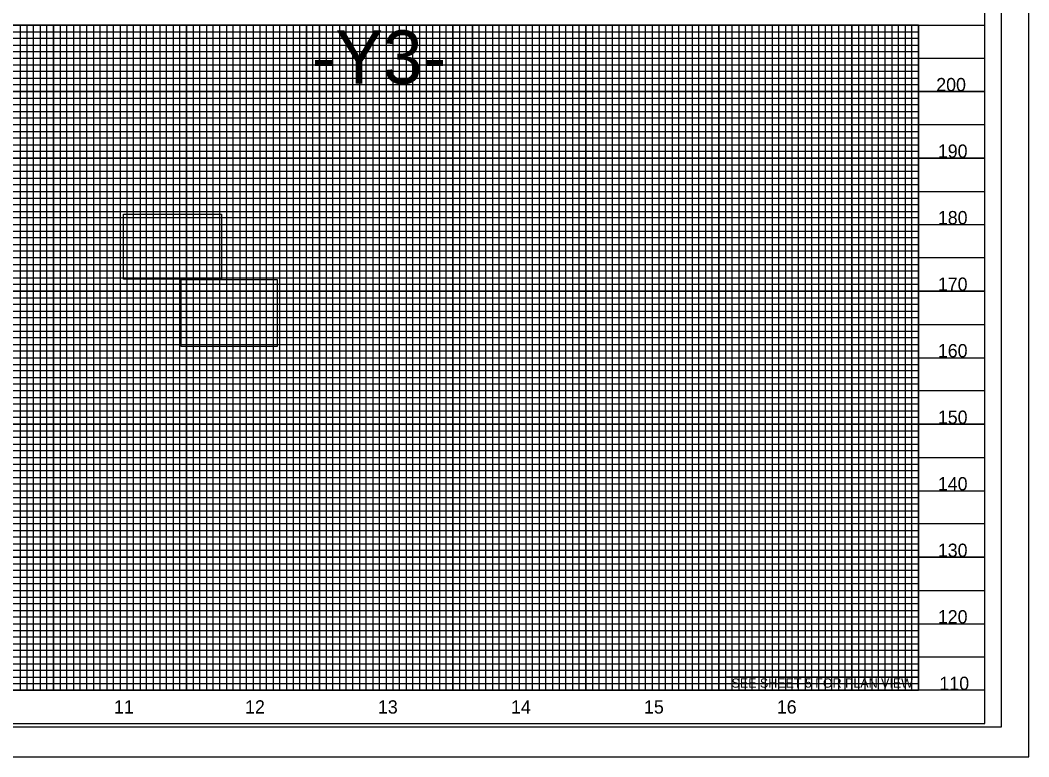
# Model space of a CAD drawing. Extents: x 1779926 to 1781626, y 618464 to 619564.
# Drawn here: x 1780868 to 1781626, y 618464 to 619018 of the extents above; entities that cross this region are included whole.
import ezdxf

# ---------------------------------------------------------------- set-up
doc = ezdxf.new("R2010")
doc.units = 0
for name, color, linetype in [('Exist Vertical Profile Horizontal Axis Label Major', 7, 'Continuous'), ('Exist Vertical Profile Vertical Axis Label', 7, 'Continuous'), ('Prop DSN Text', 7, 'Continuous'), ('Prop Grid Mask', 7, 'Continuous'), ('Sheet DOT Grid CELL', 7, 'Continuous'), ('Sheet Layout Profile Border Port 2', 7, 'Continuous'), ('Sheet Plot Border Inside CELL', 7, 'Continuous'), ('Sheet Plot Border Outside CELL', 7, 'Continuous'), ('Sheet Profile CELL', 7, 'Continuous'), ('Sheet Profile Grid Major CELL', 7, 'Continuous'), ('Sheet Profile Grid Middle CELL', 7, 'Continuous'), ('Sheet Profile Grid Minor CELL', 7, 'Continuous')]:
    doc.layers.add(name, color=color, linetype=linetype)

msp = doc.modelspace()

# ---------------------------------------------------------------- linework, layer by layer
at = {"layer": 'Prop Grid Mask'}
for points in [[(1781207.96, 619014.19), (1781083.09, 619014.19), (1781083.09, 618964.19), (1781207.96, 618964.19)], [(1780945.64, 618872.05), (1781019.12, 618872.05), (1781019.12, 618823.22), (1780945.64, 618823.22)], [(1780988.9, 618823.06), (1781061.03, 618823.06), (1781061.03, 618772.71), (1780988.9, 618772.71)], [(1781542.96, 618524.19), (1781397.96, 618524.19), (1781397.96, 618514.19), (1781542.96, 618514.19)]]:
    msp.add_lwpolyline(points, close=True, dxfattribs=at)
at = {"layer": 'Sheet DOT Grid CELL'}
for p, q in [((1780092.96, 619014.19), (1781592.85, 619014.19)), ((1780892.96, 619014.19), (1780892.96, 618514.19)), ((1780942.96, 619014.19), (1780942.96, 618514.19)), ((1780992.96, 619014.19), (1780992.96, 618514.19)), ((1781042.96, 619014.19), (1781042.96, 618514.19)), ((1781092.96, 619014.19), (1781092.96, 618514.19)), ((1781142.96, 619014.19), (1781142.96, 618514.19)), ((1781192.96, 619014.19), (1781192.96, 618514.19)), ((1781242.96, 619014.19), (1781242.96, 618514.19)), ((1781292.96, 619014.19), (1781292.96, 618514.19)), ((1781342.96, 619014.19), (1781342.96, 618514.19)), ((1781392.96, 619014.19), (1781392.96, 618514.19)), ((1781442.96, 619014.19), (1781442.96, 618514.19)), ((1781492.96, 619014.19), (1781492.96, 618514.19)), ((1781542.96, 619014.19), (1781542.96, 618514.19)), ((1780092.96, 618964.19), (1781592.85, 618964.19)), ((1780092.96, 618914.19), (1781592.85, 618914.19)), ((1780092.96, 618864.19), (1781592.85, 618864.19)), ((1780092.96, 618814.19), (1781592.85, 618814.19)), ((1780092.96, 618764.19), (1781592.85, 618764.19)), ((1780092.96, 618714.19), (1781592.85, 618714.19)), ((1780092.96, 618664.19), (1781592.85, 618664.19)), ((1780092.96, 618614.19), (1781592.85, 618614.19)), ((1780092.96, 618564.19), (1781592.85, 618564.19))]:
    msp.add_line(p, q, dxfattribs=at)
at = {"layer": 'Sheet Layout Profile Border Port 2'}
msp.add_line((1781542.96, 619014.19), (1781442.96, 619014.19), dxfattribs=at)
msp.add_lwpolyline([(1780142.96, 619014.19), (1781542.96, 619014.19), (1781542.96, 618514.19), (1780142.96, 618514.19)], close=True, dxfattribs=at)
msp.add_lwpolyline([(1781442.96, 619014.19), (1780142.96, 619014.19), (1780142.96, 618514.19), (1781542.96, 618514.19), (1781542.96, 619014.19)], dxfattribs=at)
at = {"layer": 'Sheet Plot Border Inside CELL'}
msp.add_lwpolyline([(1779938.96, 618486.64), (1781605.46, 618486.64), (1781605.46, 619541.74), (1779938.96, 619541.74)], close=True, dxfattribs=at)
at = {"layer": 'Sheet Plot Border Outside CELL'}
msp.add_lwpolyline([(1779925.96, 618464.19), (1781625.96, 618464.19), (1781625.96, 619564.19), (1779925.96, 619564.19)], close=True, dxfattribs=at)
at = {"layer": 'Sheet Profile CELL'}
for p, q in [((1780092.96, 619014.19), (1781592.96, 619014.19)), ((1781592.96, 618514.19), (1780092.96, 618514.19)), ((1780092.96, 618489.19), (1781592.96, 618489.19))]:
    msp.add_line(p, q, dxfattribs=at)
msp.add_lwpolyline([(1781592.96, 619539.19), (1780092.96, 619539.19), (1780092.96, 618489.19), (1781592.96, 618489.19)], close=True, dxfattribs=at)
at = {"layer": 'Sheet Profile Grid Major CELL'}
for p, q in [((1780892.96, 619014.19), (1780942.96, 619014.19)), ((1780992.96, 619014.19), (1781042.96, 619014.19)), ((1781092.96, 619014.19), (1781142.96, 619014.19)), ((1781192.96, 619014.19), (1781242.96, 619014.19)), ((1781292.96, 619014.19), (1781342.96, 619014.19)), ((1781392.96, 619014.19), (1781442.96, 619014.19)), ((1781492.96, 619014.19), (1781542.96, 619014.19)), ((1781492.96, 618514.19), (1781492.96, 618514.19))]:
    msp.add_line(p, q, dxfattribs=at)
for points in [[(1780842.96, 618514.19), (1780892.96, 618514.19), (1780892.96, 619014.19), (1780942.96, 619014.19), (1780942.96, 618514.19), (1780992.96, 618514.19), (1780992.96, 619014.19), (1781042.96, 619014.19), (1781042.96, 618514.19), (1781092.96, 618514.19), (1781092.96, 619014.19), (1781142.96, 619014.19), (1781142.96, 618514.19), (1781192.96, 618514.19), (1781192.96, 619014.19), (1781242.96, 619014.19), (1781242.96, 618514.19), (1781292.96, 618514.19), (1781292.96, 619014.19), (1781342.96, 619014.19), (1781342.96, 618514.19), (1781392.96, 618514.19), (1781392.96, 619014.19), (1781442.96, 619014.19), (1781442.96, 618514.19), (1781492.96, 618514.19), (1781492.96, 618514.19), (1781492.96, 619014.19), (1781542.96, 619014.19), (1781542.96, 618514.19)], [(1781592.96, 618964.19), (1780092.96, 618964.19)], [(1781592.96, 618914.19), (1780092.96, 618914.19), (1780092.96, 618864.19), (1781592.96, 618864.19)], [(1781592.96, 618814.19), (1780092.96, 618814.19), (1780092.96, 618764.19), (1781592.96, 618764.19)], [(1781592.96, 618714.19), (1780092.96, 618714.19), (1780092.96, 618664.19), (1781592.96, 618664.19)], [(1781592.96, 618614.19), (1780092.96, 618614.19), (1780092.96, 618614.19), (1780092.96, 618564.19), (1781592.96, 618564.19)], [(1781592.96, 618514.19), (1780092.96, 618514.19)]]:
    msp.add_lwpolyline(points, dxfattribs=at)
at = {"layer": 'Sheet Profile Grid Middle CELL'}
for points in [[(1780817.96, 619014.19), (1780867.96, 619014.19), (1780867.96, 618514.19), (1780917.96, 618514.19), (1780917.96, 619014.19), (1780967.96, 619014.19), (1780967.96, 618514.19), (1781017.96, 618514.19), (1781017.96, 619014.19), (1781067.96, 619014.19), (1781067.96, 618514.19), (1781117.96, 618514.19), (1781117.96, 619014.19), (1781167.96, 619014.19), (1781167.96, 618514.19), (1781217.96, 618514.19), (1781217.96, 619014.19), (1781267.96, 619014.19), (1781267.96, 618514.19), (1781317.96, 618514.19), (1781317.96, 619014.19), (1781367.96, 619014.19), (1781367.96, 618514.19), (1781417.96, 618514.19), (1781417.96, 619014.19), (1781467.96, 619014.19), (1781467.96, 618514.19), (1781517.96, 618514.19), (1781517.96, 619014.19)], [(1780092.96, 618989.19), (1781592.96, 618989.19)], [(1781592.96, 618939.19), (1780092.96, 618939.19), (1780092.96, 618889.19), (1781592.96, 618889.19)], [(1781592.96, 618839.19), (1780092.96, 618839.19), (1780092.96, 618789.19), (1781592.96, 618789.19)], [(1781592.96, 618739.19), (1780092.96, 618739.19), (1780092.96, 618689.19), (1781592.96, 618689.19)], [(1781592.96, 618639.19), (1780092.96, 618639.19), (1780092.96, 618589.19), (1781592.96, 618589.19)], [(1781592.96, 618539.19), (1780092.96, 618539.19)]]:
    msp.add_lwpolyline(points, dxfattribs=at)
at = {"layer": 'Sheet Profile Grid Minor CELL'}
for p, q in [((1780142.96, 619009.19), (1781542.96, 619009.19)), ((1781542.96, 619004.19), (1780142.96, 619004.19)), ((1780142.96, 618999.19), (1781542.96, 618999.19)), ((1781542.96, 618994.19), (1780142.96, 618994.19)), ((1780142.96, 618984.19), (1781542.96, 618984.19)), ((1781542.96, 618979.19), (1780142.96, 618979.19)), ((1780142.96, 618974.19), (1781542.96, 618974.19)), ((1781542.96, 618969.19), (1780142.96, 618969.19)), ((1780142.96, 618959.19), (1781542.96, 618959.19)), ((1781542.96, 618954.19), (1780142.96, 618954.19)), ((1780142.96, 618949.19), (1781542.96, 618949.19)), ((1781542.96, 618944.19), (1780142.96, 618944.19)), ((1780142.96, 618934.19), (1781542.96, 618934.19)), ((1781542.96, 618929.19), (1780142.96, 618929.19)), ((1780142.96, 618924.19), (1781542.96, 618924.19)), ((1781542.96, 618919.19), (1780142.96, 618919.19)), ((1780142.96, 618909.19), (1781542.96, 618909.19)), ((1781542.96, 618904.19), (1780142.96, 618904.19)), ((1780142.96, 618899.19), (1781542.96, 618899.19)), ((1781542.96, 618894.19), (1780142.96, 618894.19)), ((1780142.96, 618884.19), (1781542.96, 618884.19)), ((1781542.96, 618879.19), (1780142.96, 618879.19)), ((1780142.96, 618874.19), (1781542.96, 618874.19)), ((1781542.96, 618869.19), (1780142.96, 618869.19)), ((1780142.96, 618859.19), (1781542.96, 618859.19)), ((1781542.96, 618854.19), (1780142.96, 618854.19)), ((1780142.96, 618849.19), (1781542.96, 618849.19)), ((1781542.96, 618844.19), (1780142.96, 618844.19)), ((1780142.96, 618834.19), (1781542.96, 618834.19)), ((1781542.96, 618829.19), (1780142.96, 618829.19)), ((1780142.96, 618824.19), (1781542.96, 618824.19)), ((1781542.96, 618819.19), (1780142.96, 618819.34)), ((1780142.96, 618809.19), (1781542.96, 618809.19)), ((1781542.96, 618804.19), (1780142.96, 618804.19)), ((1780142.96, 618799.19), (1781542.96, 618799.19)), ((1781542.96, 618794.19), (1780142.96, 618794.19)), ((1780142.96, 618784.19), (1781542.96, 618784.19)), ((1781542.96, 618779.19), (1780142.96, 618779.19)), ((1780142.96, 618774.19), (1781542.96, 618774.19)), ((1781542.96, 618769.19), (1780142.96, 618769.19)), ((1780142.96, 618759.19), (1781542.96, 618759.19)), ((1781542.96, 618754.19), (1780142.96, 618754.19)), ((1780142.96, 618749.19), (1781542.96, 618749.19)), ((1781542.96, 618744.19), (1780142.96, 618744.19)), ((1780142.96, 618734.19), (1781542.96, 618734.19)), ((1781542.96, 618729.19), (1780142.96, 618729.19)), ((1780142.96, 618724.19), (1781542.96, 618724.19)), ((1781542.96, 618719.19), (1780142.96, 618719.19)), ((1780142.96, 618709.19), (1781542.96, 618709.19)), ((1781542.96, 618704.19), (1780142.96, 618704.19)), ((1780142.96, 618699.19), (1781542.96, 618699.19)), ((1781542.96, 618694.19), (1780142.96, 618694.19)), ((1780142.96, 618684.19), (1781542.96, 618684.19)), ((1781542.96, 618679.19), (1780142.96, 618679.19)), ((1780142.96, 618674.19), (1781542.96, 618674.19)), ((1781542.96, 618669.19), (1780142.96, 618669.19)), ((1780142.96, 618659.19), (1781542.96, 618659.19)), ((1781542.96, 618654.19), (1780142.96, 618654.19)), ((1780142.96, 618649.19), (1781542.96, 618649.19)), ((1781542.96, 618644.19), (1780142.96, 618644.19)), ((1780142.96, 618634.19), (1781542.96, 618634.19)), ((1781542.96, 618629.19), (1780142.96, 618629.19)), ((1780142.96, 618624.19), (1781542.96, 618624.19)), ((1781542.96, 618619.19), (1780142.96, 618619.19)), ((1780142.96, 618609.19), (1781542.96, 618609.19)), ((1781542.96, 618604.19), (1780142.96, 618604.19)), ((1780142.96, 618599.19), (1781542.96, 618599.19)), ((1781542.96, 618594.19), (1780142.96, 618594.19)), ((1780142.96, 618584.19), (1781542.96, 618584.19)), ((1781542.96, 618579.19), (1780142.96, 618579.19)), ((1780142.96, 618574.19), (1781542.96, 618574.19)), ((1781542.96, 618569.19), (1780142.96, 618569.19)), ((1780142.96, 618559.19), (1781542.96, 618559.19)), ((1781542.96, 618554.19), (1780142.96, 618554.19)), ((1780142.96, 618549.19), (1781542.96, 618549.19)), ((1781542.96, 618544.19), (1780142.96, 618544.19)), ((1780142.96, 618534.19), (1781542.96, 618534.19)), ((1781542.96, 618529.19), (1780142.96, 618529.19)), ((1780142.96, 618524.19), (1781542.96, 618524.19)), ((1780142.96, 618519.19), (1781542.96, 618519.19)), ((1781542.96, 618519.19), (1781542.96, 618519.19))]:
    msp.add_line(p, q, dxfattribs=at)
for points in [[(1780862.96, 619014.19), (1780872.96, 619014.19), (1780872.96, 618514.19), (1780877.96, 618514.19), (1780877.96, 619014.19), (1780882.96, 619014.19), (1780882.96, 618514.19), (1780887.96, 618514.19), (1780887.96, 619014.19), (1780897.96, 619014.19), (1780897.96, 618514.19), (1780902.96, 618514.19), (1780902.96, 619014.19), (1780907.96, 619014.19), (1780907.96, 618514.19), (1780912.96, 618514.19), (1780912.96, 619014.19), (1780922.96, 619014.19), (1780922.96, 618514.19), (1780927.96, 618514.19), (1780927.96, 619014.19), (1780932.96, 619014.19), (1780932.96, 618514.19), (1780937.96, 618514.19), (1780937.96, 619014.19), (1780947.96, 619014.19), (1780947.96, 618514.19), (1780952.66, 618514.74), (1780952.96, 618514.19), (1780952.96, 619014.19), (1780957.96, 619014.19), (1780957.96, 618514.19), (1780962.96, 618514.19), (1780962.96, 619014.19), (1780972.96, 619014.19), (1780972.96, 618514.19), (1780977.96, 618514.19)], [(1780977.96, 618514.19), (1780977.96, 619014.19), (1780982.96, 619014.19), (1780982.96, 618514.19), (1780987.96, 618514.19), (1780987.96, 619014.19), (1780997.96, 619014.19), (1780997.96, 618514.19), (1781002.96, 618514.19), (1781002.96, 619014.19), (1781007.96, 619014.19), (1781007.96, 618514.19), (1781012.96, 618514.19), (1781012.96, 619014.19), (1781022.96, 619014.19), (1781022.96, 618514.19), (1781027.96, 618514.19), (1781027.96, 619014.19), (1781032.96, 619014.19), (1781032.96, 618514.19), (1781037.96, 618514.19), (1781037.96, 619014.19), (1781047.96, 619014.19), (1781047.96, 618514.19), (1781052.96, 618514.19), (1781052.96, 619014.19), (1781057.96, 619014.19), (1781057.96, 618514.19), (1781062.96, 618514.19), (1781062.96, 619014.19), (1781072.96, 619014.19), (1781072.96, 618514.19), (1781077.96, 618514.19), (1781077.96, 619014.19), (1781082.96, 619014.19), (1781082.96, 618514.19), (1781087.96, 618514.19), (1781087.96, 619014.19), (1781097.96, 619014.19), (1781097.96, 618514.19), (1781102.96, 618514.19), (1781102.96, 619014.19), (1781107.96, 619014.19), (1781107.96, 618514.19), (1781112.96, 618514.19), (1781112.96, 619014.19), (1781122.96, 619014.19), (1781122.96, 618514.19), (1781127.96, 618514.19), (1781127.96, 619014.19), (1781132.96, 619014.19), (1781132.96, 618514.19), (1781137.96, 618514.19), (1781137.96, 619014.19), (1781147.96, 619014.19), (1781147.96, 618514.19), (1781152.96, 618514.19), (1781152.96, 619014.19), (1781157.96, 619014.19), (1781157.96, 618514.19), (1781162.96, 618514.19), (1781162.96, 619014.19), (1781172.96, 619014.19), (1781172.96, 618514.19), (1781177.96, 618514.19), (1781177.96, 619014.19), (1781182.96, 619014.19), (1781182.96, 618514.19), (1781187.96, 618514.19), (1781187.96, 619014.19), (1781197.96, 619014.19), (1781197.96, 618514.19), (1781202.96, 618514.19), (1781202.96, 619014.19), (1781207.96, 619014.19), (1781207.96, 618514.19), (1781212.96, 618514.19), (1781212.96, 619014.19), (1781222.96, 619014.19), (1781222.96, 618514.19), (1781227.96, 618514.19), (1781227.96, 619014.19), (1781232.96, 619014.19), (1781232.96, 618514.19), (1781237.96, 618514.19), (1781237.96, 619014.19), (1781247.96, 619014.19), (1781247.96, 618514.19), (1781252.96, 618514.19), (1781252.96, 619014.19), (1781257.96, 619014.19), (1781257.96, 618514.19), (1781262.96, 618514.19), (1781262.96, 619014.19), (1781272.96, 619014.19), (1781272.96, 618514.19), (1781277.96, 618514.19), (1781277.96, 619014.19), (1781282.96, 619014.19), (1781282.96, 618514.19)], [(1781282.96, 618514.19), (1781287.96, 618514.19), (1781287.96, 619014.19), (1781297.96, 619014.19), (1781297.96, 618514.19), (1781302.96, 618514.19), (1781302.96, 619014.19), (1781307.96, 619014.19), (1781307.96, 618514.19), (1781312.96, 618514.19), (1781312.96, 619014.19), (1781322.96, 619014.19), (1781322.96, 618514.19), (1781327.96, 618514.19), (1781327.96, 619014.19), (1781332.96, 619014.19), (1781332.96, 618514.19), (1781337.96, 618514.19), (1781337.96, 619014.19), (1781347.96, 619014.19), (1781347.96, 618514.19), (1781352.96, 618514.19), (1781352.96, 619014.19), (1781357.96, 619014.19), (1781357.96, 618514.19), (1781362.96, 618514.19), (1781362.96, 619014.19), (1781372.96, 619014.19), (1781372.96, 618514.19), (1781377.96, 618514.19), (1781377.96, 619014.19), (1781382.96, 619014.19), (1781382.96, 618514.19), (1781387.96, 618514.19), (1781387.96, 619014.19), (1781397.96, 619014.19), (1781397.96, 618514.19), (1781402.96, 618514.19), (1781402.96, 619014.19), (1781407.96, 619014.19), (1781407.96, 618514.19), (1781412.96, 618514.19), (1781412.96, 619014.19), (1781422.96, 619014.19), (1781422.96, 618514.19), (1781427.96, 618514.19), (1781427.96, 619014.19), (1781432.96, 619014.19), (1781432.96, 618514.19), (1781437.96, 618514.19), (1781437.96, 619014.19), (1781447.96, 619014.19), (1781447.96, 618514.19), (1781452.96, 618514.19), (1781452.96, 619014.19), (1781457.96, 619014.19), (1781457.96, 618514.19), (1781462.96, 618514.19), (1781462.96, 619014.19), (1781472.96, 619014.19), (1781472.96, 618514.19), (1781477.96, 618514.19), (1781477.96, 619014.19), (1781482.96, 619014.19), (1781482.96, 618514.19), (1781487.96, 618514.19), (1781487.96, 619014.19), (1781497.96, 619014.19), (1781497.96, 618514.19), (1781502.96, 618514.19), (1781502.96, 619014.19), (1781507.96, 619014.19), (1781507.96, 618514.19), (1781512.96, 618514.19), (1781512.96, 619014.19), (1781522.96, 619014.19), (1781522.96, 618514.19), (1781527.96, 618514.19), (1781527.96, 619014.19), (1781532.96, 619014.19), (1781532.96, 618514.19), (1781537.96, 618514.19), (1781537.96, 619014.19), (1781542.96, 619014.19)]]:
    msp.add_lwpolyline(points, dxfattribs=at)

# ---------------------------------------------------------------- texts
at = {"layer": 'Exist Vertical Profile Horizontal Axis Label Major'}
for s, p in [('11', (1780938.38, 618496.69)), ('12', (1781036.93, 618496.69)), ('13', (1781136.77, 618496.69)), ('14', (1781236.82, 618496.69)), ('15', (1781336.75, 618496.69)), ('16', (1781436.58, 618496.69))]:
    msp.add_text(s, height=10, dxfattribs=at).set_placement(p)
at = {"layer": 'Exist Vertical Profile Vertical Axis Label'}
for s, p in [('200', (1781556.39, 618964.44)), ('190', (1781557.59, 618914.44)), ('180', (1781557.59, 618864.44)), ('170', (1781557.59, 618814.44)), ('160', (1781557.59, 618764.44)), ('150', (1781557.59, 618714.44)), ('140', (1781557.59, 618664.44)), ('130', (1781557.59, 618614.44)), ('120', (1781557.59, 618564.44)), ('110', (1781558.79, 618514.44))]:
    msp.add_text(s, height=10, dxfattribs=at).set_placement(p)
at = {"layer": 'Prop DSN Text'}
for s, height, p in [('-Y3-', 40, (1781087.01, 618970.14)), ('SEE SHEET 5 FOR PLAN VIEW', 7, (1781402.54, 618516.14))]:
    msp.add_text(s, height=height, dxfattribs=at).set_placement(p)

doc.saveas('drawing.dxf')
